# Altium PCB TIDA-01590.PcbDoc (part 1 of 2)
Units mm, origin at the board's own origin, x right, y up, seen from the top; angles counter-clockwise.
Board outline 129.16 x 83.44 mm, 2 copper layers (Top Layer, Bottom Layer), stack 1.646 mm thick; 71 components, 28 nets, 172 pads, 183 vias.
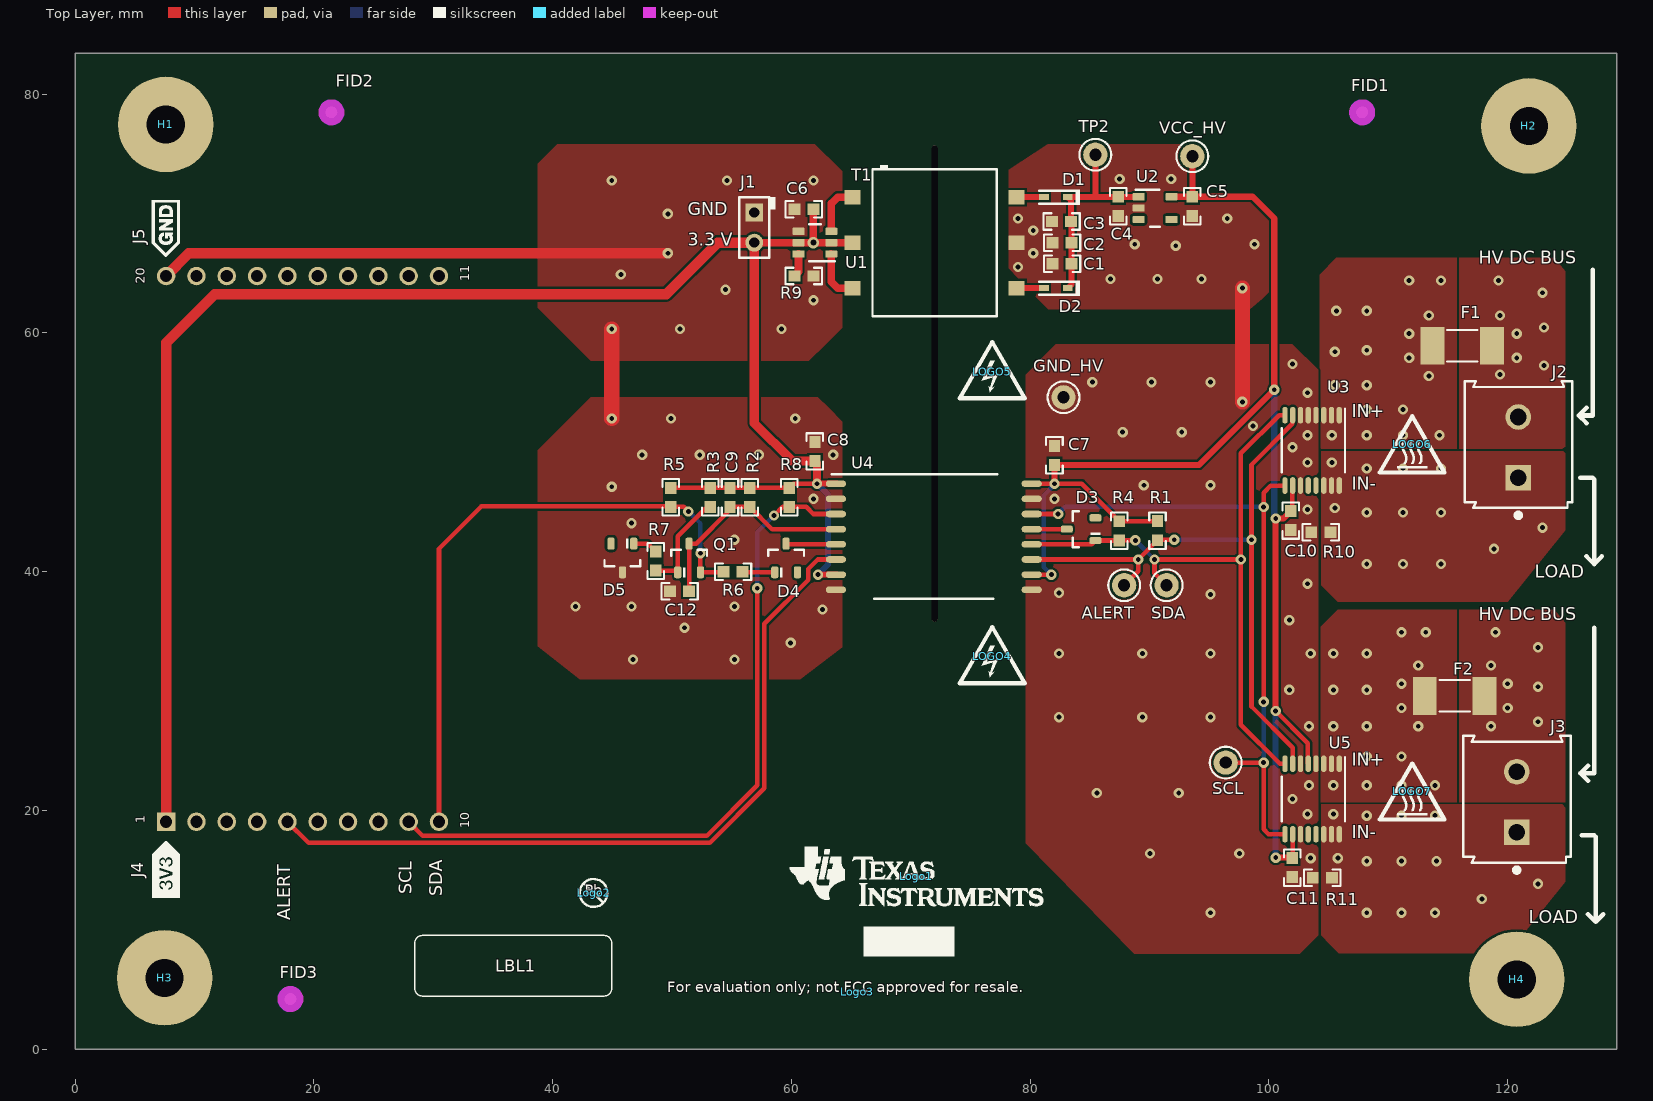
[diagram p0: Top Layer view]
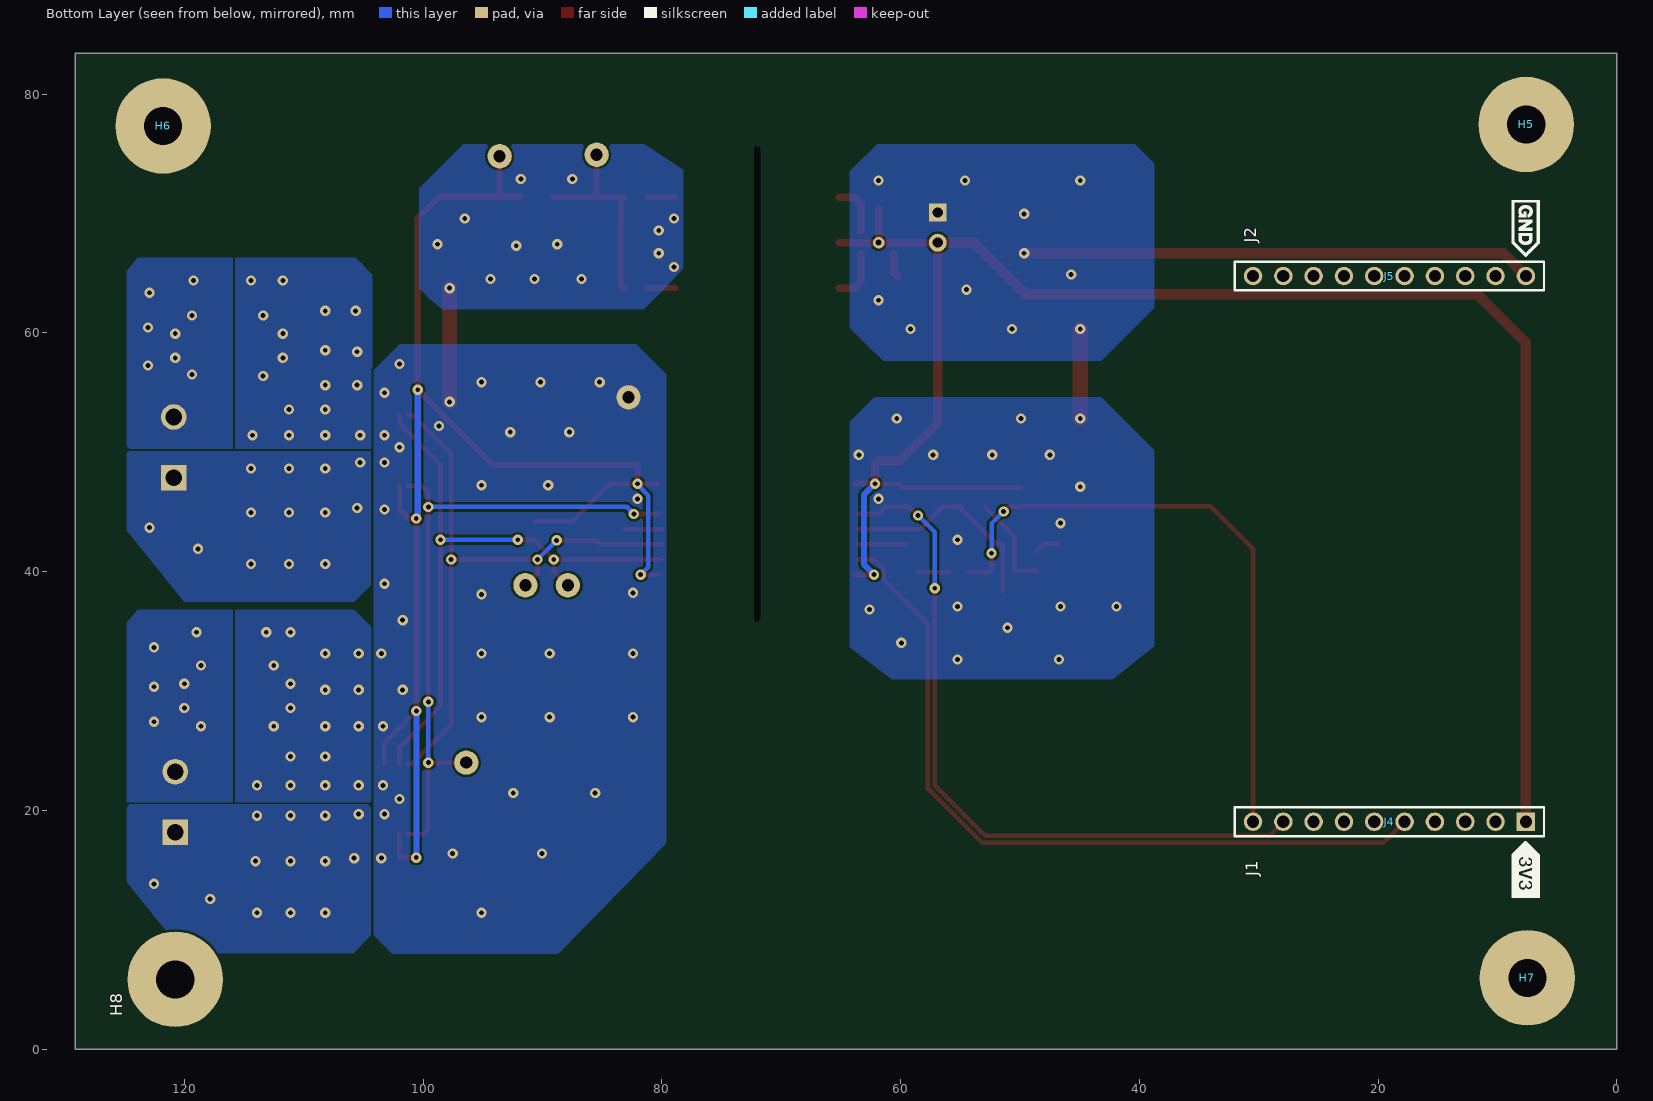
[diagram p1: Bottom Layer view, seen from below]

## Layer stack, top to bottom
Top Solder: solder mask 0.0102, Solder Resist, Dk 3.5
Top Layer: signal copper 0.0711
Dielectric1: core 1.5037, FR-4, Dk 4.8
Bottom Layer: signal copper 0.0711
Bottom Solder: solder mask 0.0102, Solder Resist, Dk 3.5

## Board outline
0,0 129.159,0 129.159,83.439 0,83.439

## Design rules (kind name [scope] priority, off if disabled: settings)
AcuteAngle [All] p1: minimum=4.50000000000000E+0001 checktracksonly=FALSE
AssemblyTestPointUsage [All] p1: valid=2
BoardOutlineClearance BoardOutlineClearance_MountingHoles [OnCopper and InComponentClass('Mounting Holes')] p1: gap=1.016
BoardOutlineClearance BoardOutlineClearance_Poly [OnCopper and IsPoly] p2: gap=0.635
BoardOutlineClearance [OnCopper and Not InComponentClass('Logo') and not InComponentClass('FiducialMark') and not InRegion(1000,500,4000,800) and not InPoly] p3: gap=1.905
Clearance Clearance_Keepouts [((IsTrack Or IsArc) And Not InPoly) And IsFree and IsKeepOut vs ((IsTrack Or IsArc) And Not InPoly) And IsFree and IsKeepOut] p1: gap=0
Clearance Clearance_Poly [InPolygon] p2: gap=0.203
Clearance [All] p3: gap=0.203 except(0.178: Track-THPad SMDPad-SMDPad)
ComponentClearance ComponentClearance_MountingHoles_FiducialMarks [InComponentClass('Mounting Holes') vs InComponentClass('FiducialMark')] p1: gap=1.27 collisioncheckmode=3 verticalgap=0.254 showdistances=FALSE
ComponentClearance ComponentClearance_Shunt [InComponentClass('Header') vs InComponentClass('Shunt')] p2: gap=0 collisioncheckmode=3 verticalgap=0 showdistances=FALSE
ComponentClearance ComponentClearance_Logo [InComponentClass('Logo')] p3: gap=1.27 collisioncheckmode=3 verticalgap=0.254 showdistances=FALSE
ComponentClearance ComponentClearance_ScrewToNut [(HasFootprint('NY PMS 440 0025 PH')) vs (HasFootprint('Keystone_1902C'))] p4: gap=0.127 collisioncheckmode=3 verticalgap=0.254 showdistances=FALSE
ComponentClearance ComponentClearance_MountingHoles [InComponentClass('Mounting Holes')] p5: gap=6.35 collisioncheckmode=3 verticalgap=2540 showdistances=FALSE
ComponentClearance ComponentClearance_SmallPassives [HasFootprint('0201*') or HasFootprint('0402*') or HasFootprint('0508') or HasFootprint('0603*') or HasFootprint('0612') or HasFootprint('0805*') or HasFootprint('0815*') or HasFootprint('0830*') or HasFootprint('1206*') or HasFootprint('1210*') or HasFootprint('1808*') or HasFootprint('1812*') or HasFootprint('1825*') or HasFootprint('2010*') or HasFootprint('2220*') or HasFootprint('2225*') or HasFootprint('2512*') or HasFootprint('2728*') or HasFootprint('3518*') vs HasFootprint('0201*') or HasFootprint('0402*') or HasFootprint('0508') or HasFootprint('0603*') or HasFootprint('0612') or HasFootprint('0805*') or HasFootprint('0815*') or HasFootprint('0830*') or HasFootprint('1206*') or HasFootprint('1210*') or HasFootprint('1808*') or HasFootprint('1812*') or HasFootprint('1825*') or HasFootprint('2010*') or HasFootprint('2220*') or HasFootprint('2225*') or HasFootprint('2512*') or HasFootprint('2728*') or HasFootprint('3518*')] p6: gap=0.38 collisioncheckmode=3 verticalgap=0.254 showdistances=FALSE
ComponentClearance ComponentClearance_THtoSMT [IsThruComponent vs IsSMTComponent] p7: gap=1.016 collisioncheckmode=3 verticalgap=0.762 showdistances=FALSE
ComponentClearance ComponentClearance_THtoTH [IsThruComponent vs IsThruComponent] p8: gap=0.762 collisioncheckmode=3 verticalgap=0.762 showdistances=FALSE
ComponentClearance [All] p9: gap=0.762 collisioncheckmode=3 verticalgap=0.254 showdistances=FALSE
DiffPairsRouting [All] p1: maxlimit=2.54 minlimit=0.254 mostfreqgap=0.254 toplayer_minwidth=0.381 toplayer_maxwidth=0.381 toplayer_prefwidth=0.381 bottomlayer_minwidth=0.381 bottomlayer_maxwidth=0.381 bottomlayer_prefwidth=0.381 maxuncoupledlength=25.4
FabricationTestPointUsage TestPointUsage [All] p1: valid=2 allowmultiple=FALSE
FabricationTestpoint Testpoint [All] p1: side=3 testpointundercomponent=TRUE minsize=1.016 maxsize=2.54 preferedsize=1.524 minholesize=0 maxholesize=1.016 preferedholesize=0.813 testpointgrid=0.025 allowsidetop=TRUE allowsidebottom=TRUE usegrid=TRUE gridtolerance=0
FanoutControl Fanout_LCC [IsLCC] p1: bgadir=Out bgaviamode=Centered fanoutstyle=Auto fanoutdirection=Alternating viagrid=0.025 // Fanout_LCC (Default Rule)
FanoutControl Fanout_BGA [IsBGA] p2: bgadir=Out bgaviamode=Centered fanoutstyle=Auto fanoutdirection=Alternating viagrid=0.025 // Fanout_BGA (Default Rule)
FanoutControl Fanout_Default [All] p4: bgadir=Out bgaviamode=Centered fanoutstyle=Auto fanoutdirection=Alternating viagrid=0.025 // Fanout_Default (Default Rule)
FanoutControl Fanout_Small [(CompPinCount < 5)] p5: bgadir=Out bgaviamode=Centered fanoutstyle=Auto fanoutdirection=OutThenIn viagrid=0.025 // Fanout_Small (Default Rule)
HoleSize [All] p1: absolutevalues=TRUE maxlimit=6.375 minlimit=0.2 maxpercent=80.000 minpercent=20.000
MinimumAnnularRing MinimumAnnularRing_ThermalPadVias [IsVia and InAnyComponent] p1: minimumring=0.15
MinimumAnnularRing [All] p2: minimumring=0.203
MinimumSolderMaskSliver MinimumSolderMaskSliver_Logo [InComponentClass('Logo') vs InComponentClass('Logo')] p1: minsoldermaskwidth=0.018
MinimumSolderMaskSliver [All] p2: minsoldermaskwidth=0.1
PlaneConnect [All] p1: planeconnectstyle=Relief reliefexpansion=0.254 reliefentries=4 reliefconductorwidth=0.254 reliefairgap=0.254
PolygonConnect [All] p1: connectstyle=Direct reliefconductorwidth=0.254 reliefentries=4 polygonreliefangle="90 Angle" airgapwidth=0.254
RoutingVias ThermalPadVias [IsVia and InAnyComponent] p1: holewidth=0.2 width=0.5 viastyle="Through Hole" minholewidth=0.2 minwidth=0.5 maxholewidth=0.33 maxwidth=0.6
RoutingVias [All] p2: holewidth=0.406 width=0.864 viastyle="Through Hole" minholewidth=0.2 minwidth=0.66 maxholewidth=1.016 maxwidth=1.651
SilkToBoardRegionClearance [Not ((IsComment or IsDesignator) And (Hide <> 'False')) and not InRegion(1000,500,4000,800)] p1:
SilkToSilkClearance SilkToSilkClearance_Pb-FreeLogo [(HasFootprint('Pb-Free_Overlay_Medium') OR HasFootprint('Pb-Free_Overlay_Small')) vs (HasFootprint('Pb-Free_Overlay_Medium') OR HasFootprint('Pb-Free_Overlay_Small'))] p1: silktosilkclearance=0
SilkToSilkClearance [All] p2: silktosilkclearance=0.102
SilkToSolderMaskClearance SilkToComponentPadClearance [(IsPad or IsFill or IsRegion) and InAnycomponent] p1: minsilkscreentomaskgap=0.127 clearancetoexposedcopper=TRUE
SilkToSolderMaskClearance "Silk to Solder Mask Opening" [All] p2: minsilkscreentomaskgap=0.102 clearancetoexposedcopper=FALSE
SolderMaskExpansion [All] p1: expansion=0.03
Width [All] p1: maxlimit=2.54 minlimit=0.152 preferedwidth=0.254 checkconnectedcopper=TRUE
15 further rules are at their usual default settings.

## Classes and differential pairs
component class Label: LBL1
component class AssemblyNote: ZZ1 ZZ2 ZZ3 ZZ4
component class FiducialMark: FID1 FID2 FID3
component class EVM_Hardware: FID1 FID2 FID3 H1 H2 H3 H4 H5 H6 H7 H8 LBL1 Logo1 Logo2 Logo3 LOGO4 LOGO5 LOGO6 LOGO7 ZZ1 ZZ2 ZZ3 ZZ4
component class Logo: Logo1
component class "Mounting Holes": H1 H2 H3 H4
component class Current_Sense: ALERT C1 C2 C3 C4 C5 C6 C7 C8 C9 C10 C11 C12 D1 D2 D3 D4 D5 F1 F2 GND_HV J1 J2 J3 J4 J5 J6 Q1 R1 R2 R3 R4 R5 R6 R7 R8 R9 R10 R11 SCL SDA T1 TP2 U1 U2 U3 U4 U5 VCC_HV
component class Header: J1

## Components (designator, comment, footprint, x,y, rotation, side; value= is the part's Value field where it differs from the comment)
ALERT "5000" Keystone5000 87.884,38.862 r90 top (schematic designator TP4)
C1 "GRM188R61C106MAALD" 0603 82.677,65.786 r180 top
C2 "C0603C105K8PACTU" 0603 82.677,67.564 r0 top
C3 "GRM188R71C104KA01D" 0603 82.639,69.342 r180 top
C4 "C1608X7R1E105K080AB" 0603 87.376,70.612 r270 top
C5 "C1608X7R1A225K080AC" 0603 93.599,70.612 r270 top
C6 "GRM188R61C106MAALD" 0603 61.049,70.358 r180 top
C7 "GRM188R71C104KA01D" 0603 82.042,49.746 r270 top
C8 "GRM188R71C104KA01D" 0603 61.976,50.076 r90 top
C9 "0603ZC102KAT2A" 0603 54.864,46.228 r270 top
C10 "GRM188R71C104KA01D" 0603 101.854,44.285 r270 top
C11 "GRM188R71C104KA01D" 0603 101.981,15.202 r270 top
C12 "0603ZC100KAT2A" 0603 50.635,38.354 r180 top
D1 "RB751S40" Fairchild_SOD-523F 82.169,71.374 r180 top
D2 "RB751S40" Fairchild_SOD-523F 82.169,63.754 r180 top
D3 "BAS40-7-F" SOT-23 84.277,43.561 r180 top
D4 "BAS40-7-F" SOT-23 59.563,41.148 r90 top
D5 "BAS40-7-F" SOT-23 45.847,41.148 r270 top
F1 "SSQ 15" Fuse_SSQ 116.205,58.928 r180 top
F2 "SSQ 15" Fuse_SSQ 115.57,29.591 r180 top
FID1 "Fiducial" Fiducial10-20 107.823,78.486 r0 top
FID2 "Fiducial" Fiducial10-20 21.463,78.486 r0 top
FID3 "Fiducial" Fiducial10-20 18.034,4.191 r0 top
GND_HV "5001" Keystone5001 82.804,54.61 r90 top (schematic designator TP3)
H1 "NY PMS 440 0025 PH" "NY PMS 440 0025 PH" 7.593,77.47 r0 top locked
H2 "NY PMS 440 0025 PH" "NY PMS 440 0025 PH" 121.793,77.343 r0 top locked
H3 "NY PMS 440 0025 PH" "NY PMS 440 0025 PH" 7.493,5.969 r0 top locked
H4 "NY PMS 440 0025 PH" "NY PMS 440 0025 PH" 120.777,5.842 r180 top
H5 "1902C" Keystone_1902C#1 7.593,77.47 r180 bottom locked
H6 "1902C" Keystone_1902C#1 121.793,77.343 r180 bottom locked
H7 "1902C" Keystone_1902C#1 7.493,5.969 r180 bottom locked
H8 "1902C" Keystone_1902C#2 120.777,5.842 r0 bottom
J1 "800-10-002-10-001000" Mill-Max_800-10-002-10-001000 56.896,68.834 r270 top
J2 "282841-2" TEC_282841-2 120.904,50.419 r90 top
J3 "282841-2" TEC_282841-2 120.777,20.701 r90 top
J4 "SSQ-110-03-F-S" BoosterPack_20pin_J1 19.05,19.05 r270 bottom
J5 "SSQ-110-03-F-S" BoosterPack_20pin_J2 19.05,64.77 r270 bottom
LBL1 "Size: 0.65\" x 0.20 \"" Label_650x200 36.703,6.985 r0 top
Logo1 "Texas Instruments" TI_Stacked_Overlay_Small 70.485,14.478 r0 top
Logo2 "Pb-Free Symbol" Pb-Free_Overlay_Small 43.434,13.081 r0 top
Logo3 "FCC disclaimer" FCC_disclaimer 65.532,4.826 r0 top
LOGO4 "DANGER HIGH VOLTAGE" IEC_HighVoltage_Small 76.835,32.893 r0 top
LOGO5 "DANGER HIGH VOLTAGE" IEC_HighVoltage_Small 76.835,56.769 r0 top
LOGO6 "CAUTION HOT SURFACE" IEC_HotSurface_Small 112.014,50.673 r0 top
LOGO7 "CAUTION HOT SURFACE" IEC_HotSurface_Small 112.014,21.59 r0 top
Q1 "MMBT3904" SOT-23 51.435,41.148 r90 top
R1 "RC0603FR-077K5L" 0603 90.678,43.434 r90 top
R2 "RT0603BRD073K12L" 0603 56.515,46.228 r270 top
R3 "RT0603BRD072K49L" 0603 53.213,46.228 r90 top
R4 "RT0603BRD071K1L" 0603 87.46,43.423 r90 top
R5 "RT0603BRD071K45L" 0603 49.911,46.228 r90 top
R6 "RT0603BRD0784R5L" 0603 55.118,40.005 r180 top
R7 "RT0603BRD07612RL" 0603 48.641,40.894 r270 top
R8 "RT0603BRD072KL" 0603 59.817,46.228 r90 top
R9 "CRCW06030000Z0EA" 0603 61.049,64.77 r0 top
R10 "CRCW06030000Z0EA" 0603 104.356,43.307 r180 top
R11 "CRCW06030000Z0EA" 0603 104.483,14.351 r180 top
SCL "5000" Keystone5000 96.393,24.003 r90 top (schematic designator TP6)
SDA "5000" Keystone5000 91.44,38.862 r90 top (schematic designator TP5)
T1 "750315240" Wurth_750315240 72.009,67.564 r0 top
TP2 "5000" Keystone5000 85.471,74.93 r90 top
U1 "SN6505ADBVR" DBV0006A_N 61.976,67.564 r180 top
U2 "TPS70933DBVR" DBV0005A_N 90.478,70.459 r0 top
U3 "INA260AIPWR" PW0016A_N 103.632,50.165 r270 top
U4 "ISO7842DWW" DWW0016A_L 71.937,42.926 r0 top
U5 "INA260AIPWR" PW0016A_N 103.632,20.955 r270 top
VCC_HV "5000" Keystone5000 93.599,74.803 r270 top (schematic designator TP1)
ZZ1 "This Assembly Note is for PCB labels only" AssemblyNoteLabel 4.699,97.485 r0 top
ZZ2 "These assemblies are ESD sensitive, ESD precautions shall be observed." AssemblyNote 4.699,94.719 r0 top
ZZ3 "These assemblies must be clean and free from flux and all contaminants. Use of no clean flux is not acceptable." AssemblyNote 4.699,92.47 r0 top
ZZ4 "These assemblies must comply with workmanship standards IPC-A-610 Class 2, unless otherwise specified." AssemblyNote 4.699,90.221 r0 top

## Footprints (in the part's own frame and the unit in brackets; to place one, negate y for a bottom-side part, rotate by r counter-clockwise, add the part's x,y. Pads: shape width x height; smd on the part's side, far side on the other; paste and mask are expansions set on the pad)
0603 [mm] "0603 from SM-752 data"
  rect 1x0.95 smd: 1(-0.8,0) 2(0.8,0)
  silkscreen extent -1.52,-0.69 1.52,0.69, body extent -0.87,-0.47 0.87,0.47, height 1
AssemblyNote [mm] "Assembly Note"
AssemblyNoteLabel [mm] "Assembly Note for PCB Labels"
BoosterPack_20pin_J1 [mm] "Receptacle, 2.54mm, 10x1, TH"
  rrect6% 1.55x1.55 hole 1.02: 1(0,11.43)
  round 1.55 hole 1.02: 2(0,8.89) 3(0,6.35) 4(0,3.81) 5(0,1.27) 6(0,-1.27) 7(0,-3.81) 8(0,-6.35) 9(0,-8.89) 10(0,-11.43)
  silkscreen extent -1.21,-12.95 6.35,12.95, body extent -1.21,-12.95 1.21,12.95, height 8.51
BoosterPack_20pin_J2 [mm] "Receptacle, 2.54mm, 10x1, TH"
  round 1.55 hole 1.02: 11(0,-11.43) 12(0,-8.89) 13(0,-6.35) 14(0,-3.81) 15(0,-1.27) 16(0,1.27) 17(0,3.81) 18(0,6.35) 19(0,8.89) 20(0,11.43)
  silkscreen extent -6.35,-12.95 1.21,12.95, body extent -1.21,-12.95 1.21,12.95, height 8.51
DBV0005A_N [mm] "SOT23, 5-Leads, Body 2.9x1.6mm, Pitch 0.95mm, Lead Span 2.8mm, IPC Medium Density"
  rrect17% 1x0.6 smd: 1(-1.375,0.95) 2(-1.375,0) 3(-1.375,-0.95) 4(1.375,-0.95) 5(1.375,0.95)
  silkscreen extent -1.62,-1.55 0.38,1.55, body extent -1.42,-1.46 1.42,1.46, height 1.09
DBV0006A_N [mm] "SOT23, 6-Leads, Body 2.9x1.6mm, Pitch 0.95mm, Lead Span 2.8mm, IPC Medium Density"
  rrect17% 1x0.6 smd: 1(-1.375,0.95) 2(-1.375,0) 3(-1.375,-0.95) 4(1.375,-0.95) 5(1.375,0) 6(1.375,0.95)
  silkscreen extent -1.67,-1.55 0.5,1.55, body extent -1.42,-1.46 1.42,1.46, height 1.12
DWW0016A_L [mm] "SOP, 16-Leads, Body 10.30x14.00mm, Pitch 1.27mm, IPC High Density"
  oval 1.7x0.55 smd: 1(-8.2,4.445) 2(-8.2,3.175) 3(-8.2,1.905) 4(-8.2,0.635) 5(-8.2,-0.635) 6(-8.2,-1.905) 7(-8.2,-3.175) 8(-8.2,-4.445) 9(8.2,-4.445) 10(8.2,-3.175) 11(8.2,-1.905) 12(8.2,-0.635) 13(8.2,0.635) 14(8.2,1.905) 15(8.2,3.175) 16(8.2,4.445)
  silkscreen extent -8.57,-5.2 5.33,5.22, body extent -8.61,-5.15 8.66,5.15, height 2.47
Fairchild_SOD-523F [mm] "SMD, 2-Leads, Body 1.2x0.8mm"
  rect 0.8x0.5 smd: 1(-1,0) 2(1,0)
  silkscreen extent -2.03,-0.65 1.4,0.65, body extent -0.65,-0.45 0.65,0.45, height 0.7
FCC_disclaimer [mm]
Fiducial10-20 [mm]
  round 1 smd mask+0.5: 1(0,0)
  Top Layer keep-out circle w1.178: c0,0 r0.5
Fuse_SSQ [mm] "Bel Fuse"
  rect 2x3.18 smd: 1(-2.5,0) 2(2.5,0)
  silkscreen extent -1.27,-1.32 1.27,1.32, body extent -3.17,-1.32 3.17,1.32, height 2.64
IEC_HighVoltage_Small [mm]
  silkscreen extent -2.72,-2.24 2.72,2.47
IEC_HotSurface_Small [mm]
  silkscreen extent -2.72,-2.36 2.72,2.35
Keystone5000 [mil] "For Keystone 500x miniature loop terminals"
  round 80 hole 40: 1(0,0)
  silkscreen extent -52,-52 52,52, body extent -49,-49 49,49, height 182
Keystone5001 [mil] "For Keystone 500x miniature loop terminals"
  round 80 hole 40: 1(0,0)
  silkscreen extent -52,-52 52,52, body extent -49,-49 49,49, height 182
Keystone_1902C#1 [mm] "Hex Standoff, 4-40 threaded, nylon"
  body extent -3.68,-3.2 3.71,3.2, height 12.73
Keystone_1902C#2 [mm] "Hex Standoff, 4-40 threaded, nylon"
  round 0.025 on Mech4: 0(0,0)
  body extent -3.68,-3.2 3.71,3.2, height 12.73
Label_650x200 [mm] "Thermal Transfer Label"
  silkscreen extent -8.25,-2.54 8.25,2.54, body extent -8.26,-2.54 8.26,2.54, height 0.03
Mill-Max_800-10-002-10-001000 [mm] "Mill-Max"
  rect 1.5x1.5 hole 0.85: 1(-1.27,0)
  round 1.5 hole 0.85: 2(1.27,0)
  silkscreen extent -2.54,-1.27 2.54,1.78, body extent -2.54,-1.27 2.54,1.27, height 8.13
"NY PMS 440 0025 PH" [mm] "4-40 nylon screw and mounting hole"
  round 8 hole 3.2: 1(0,0)
  body extent -3.3,-3.3 3.3,3.3, height 2.69
Pb-Free_Overlay_Small [mm]
  silkscreen extent -1.16,-1.17 1.17,1.17
PW0016A_N [mm] "TSOP, 16-Leads, Body 5x4.4mm, Pitch 0.65mm, IPC Medium Density"
  oval 1.4x0.45 smd: 1(-2.95,2.275) 2(-2.95,1.625) 3(-2.95,0.975) 4(-2.95,0.325) 5(-2.95,-0.325) 6(-2.95,-0.975) 7(-2.95,-1.625) 8(-2.95,-2.275) 9(2.95,-2.275) 10(2.95,-1.625) 11(2.95,-0.975) 12(2.95,-0.325) 13(2.95,0.325) 14(2.95,0.975) 15(2.95,1.625) 16(2.95,2.275)
  silkscreen extent -3.5,-2.55 1.85,2.75, body extent -3.21,-2.5 3.21,2.5, height 1
SOT-23 [mm] "SOT23, 3-Leads, Body 2.9x1.3mm, Pitch 0.95mm, Lead Span 2.5mm, IPC Medium Density"
  rrect50% 1x0.6 smd: 1(-1.2,0.95) 2(-1.2,-0.95) 3(1.2,0)
  silkscreen extent -1.62,-1.5 0.7,1.5, body extent -1.16,-1.45 1.21,1.45, height 1
TEC_282841-2 [mm] "TE Connectivity"
  rect 2.15x2.15 hole 1.4: 1(-2.54,0)
  round 2.15 hole 1.4: 2(2.54,0)
  silkscreen extent -5.9,-4.52 5.55,4.48, body extent -5.08,-4.53 5.58,4.47, height 15.2
TI_Stacked_Overlay_Small [mm]
  silkscreen extent -10.63,-2.49 10.63,2.49
Wurth_750315240 [mm] "SMD, 6-Leads, Body 10.41x12.32mm"
  rect 1.335x1.215 smd: 1(-6.87,3.81) 2(-6.87,0) 3(-6.87,-3.81) 4(6.87,-3.81) 5(6.87,0) 6(6.87,3.81)
  silkscreen extent -5.21,-6.16 5.21,6.5, body extent -7.43,-6.16 7.43,6.16, height 11.06

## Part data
ALERT SCL SDA TP2 VCC_HV: "Test Point, Miniature, Red, TH"
C1 C6: "CAP, CERM, 10 µF, 16 V, +/- 20%, X5R, 0603"
C2: "CAP, CERM, 1 µF, 10 V, +/- 10%, X5R, 0603"
C3 C7 C8 C10 C11: "CAP, CERM, 0.1 µF, 16 V, +/- 10%, X7R, 0603"
C4: "CAP, CERM, 1 µF, 25 V, +/- 10%, X7R, 0603"
C5: "CAP, CERM, 2.2 µF, 10 V, +/- 10%, X7R, 0603"
C9: "CAP, CERM, 1000 pF, 10 V, +/- 10%, X7R, 0603"
C12: "CAP, CERM, 10 pF, 10 V, +/- 10%, X7R, 0603"
D1 D2: "Diode, Schottky, 40 V, 0.03 A, SOD-523F"
D3 D4 D5: "Diode, Schottky, 40 V, 0.2 A, SOT-23"
F1 F2: "Fuse, 15 A, SMD"
FID1 FID2 FID3: "Fiducial mark.  There is nothing to buy or mount."
GND_HV: "Test Point, Miniature, Black, TH"
H1 H2 H3 H4: "Machine Screw, Round, #4-40 x 1/4, Nylon, Philips panhead"
H5 H6 H7 H8: "Standoff, Hex, 0.5\"L #4-40 Nylon"
J1: "Header, 100mil, 2x1, TH"
J2 J3: "Terminal Block, 2x1, 5.08mm, TH"
J4: library part BoosterPack_20pin_J1, "Receptacle, 2.54mm, 10x1, Gold, TH"
J5: library part BoosterPack_20pin_J2, "Receptacle, 2.54mm, 10x1, Gold, TH"
LBL1: library part THT-14-423-10, "Thermal Transfer Printable Labels, 0.650\" W x 0.200\" H - 10,000 per roll"
Logo1: library part TI_Logo, "Texas Instrument Corporate Signature"
Logo2: library part Pb-Free
Logo3: library part FCC_disclaimer, "FCC_disclaimer"
LOGO4 LOGO5: library part IEC_HighVoltage, "IEC 61010-1 High Voltage Warning"
LOGO6 LOGO7: library part IEC_HotSurface, "IEC 61010-1 Hot Surface Warning"
Q1: library part "MMBT3904, Fairchild Semiconductor", "Transistor, NPN, 40 V, 0.2 A, SOT-23"
R1: "RES, 7.50 k, 1%, 0.1 W, 0603"
R2: "RES, 3.12 k, 0.1%, 0.1 W, 0603"
R3: "RES, 2.49 k, 0.1%, 0.1 W, 0603"
R4: "RES, 1.10 k, 0.1%, 0.1 W, 0603"
R5: "RES, 1.45 k, 0.1%, 0.1 W, 0603"
R6: "RES, 84.5, 0.1%, 0.1 W, 0603"
R7: "RES, 612, 0.1%, 0.1 W, 0603"
R8: "RES, 2.00 k, 0.1%, 0.1 W, 0603"
R9 R10 R11: "RES, 0, 5%, 0.1 W, 0603"
T1: "Transformer, 110 uH, SMT"
U1: "Low-Noise 1-A Transformer Driver for Isolated Power Supplies, Internal Clock-160kHz, DBV0006A (SOT-23-6)"
U2: "150-mA, 30-V, Ultra-Low IQ, Wide Input Low-Dropout Regulator with Reverse Current Protection, DBV0005A (SOT-23-5)"
U3 U5: "Integrated Shunt High-Side or Low-Side Measurement, Bi-Directional Current and Power Monitor with I2C Compatible Interface, PW0016A (TSSOP-16)"
U4: "5.7 kVrms, 100 Mbps, Reinforced 4-Channel 2/2 Digital Isolator, DWW0016A (SOIC-16)"
ZZ1: library part AssemblyNoteLabel
ZZ2 ZZ3 ZZ4: library part AssemblyNote

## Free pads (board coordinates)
  oval 0.483x39.878 hole 0.508 slot 39.878 at 90 deg unplated mask+0.254: 0(72.009,55.753)

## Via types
v1: diameter 0.864, hole 0.406, Top Layer to Bottom Layer, tented both sides, 182 vias
v2: diameter 0.965, hole 0.508, Top Layer to Bottom Layer, tented both sides, 1 vias

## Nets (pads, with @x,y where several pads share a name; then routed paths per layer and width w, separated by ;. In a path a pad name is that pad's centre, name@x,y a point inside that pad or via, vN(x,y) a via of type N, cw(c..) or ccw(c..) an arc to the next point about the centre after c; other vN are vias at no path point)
ALERT: J4.5 U4.6 | length 65
  Top Layer w0.381: J4.5@17.78,19.05 19.558,17.272 53.15,17.272 57.734,21.856 57.734,35.636 61.404,39.306 61.404,40.226 62.2,41.021 U4.6@63.555,41.021
ALERT_HV: ALERT.1 R1.1 U3.7 U4.11 U5.7 | length 54
  Top Layer w0.254: U4.11@79.955,41.021 U4.11@80.209,41.021
  Top Layer w0.381: U4.11@80.209,41.021 v1(89.065,41.021) ; ALERT.1@87.884,38.862 89.065,40.043 v1(89.065,41.021) ; v1(92.075,42.672) 90.716,42.672 R1.1@90.678,42.634 v1(89.065,41.021) ; U5.7@101.976,23.936 U5.7@102.007,23.905 102.007,25.247 98.552,28.702 v1(98.552,42.672) 98.552,48.96 101.976,52.384 101.976,53.084 U3.7@102.007,53.115
  Bottom Layer w0.381: v1(92.075,42.672) v1(98.552,42.672)
GND: C6.2 C8.2 C12.2 D5.3 J1.1 J5.20 R9.2 U1.4 U4.2 U4.8 | length 50.3
  Top Layer w0.889: J5.20@7.62,64.77 9.525,66.675 v1(49.657,66.675)
  Top Layer w1.27: v1(44.958,52.832) v1(44.958,60.325)
  other v1: 46.736,32.639 55.245,32.639 59.944,34.036 51.054,35.306 62.611,36.83 41.91,37.084 46.609,37.084 55.245,37.084 55.245,42.672 46.609,44.069 61.849,46.101 44.958,47.117 47.498,49.784 52.324,49.784 57.277,49.784 63.5,49.784 49.911,52.832 60.325,52.832 50.673,60.325 59.182,60.325 61.849,62.738 54.483,63.627 45.72,64.897 49.657,69.977 44.958,72.771 54.61,72.771 61.849,72.771
GND_HV: C1.2 C2.1 C3.2 C4.2 C5.2 C7.1 C10.2 C11.2 GND_HV.1 R10.2 R11.2 T1.5 U2.2 U3.4 U3.5 U3.6 U3.11 U4.9 U4.15 U5.4 U5.6 U5.11 | length 9.5
  Top Layer w1.27: v1(97.79,54.229) v1(97.79,63.754)
  other v1: 95.123,11.43 103.505,16.002 90.043,16.383 97.536,16.383 103.251,19.685 101.981,20.955 85.598,21.463 92.456,21.463 103.378,22.098 103.378,27.051 82.423,27.813 89.408,27.813 95.123,27.813 101.727,30.099 82.423,33.147 89.408,33.147 95.123,33.147 103.505,33.147 101.727,35.941 95.123,38.1 82.423,38.227 103.251,38.989 103.251,45.212 82.042,46.101 89.535,47.244 95.123,47.244 103.251,49.149 101.981,50.419 103.251,51.435 87.757,51.689 92.71,51.689 98.679,52.197 103.251,54.991 85.217,55.88 90.17,55.88 95.123,55.88 101.981,57.404 86.741,64.516 90.678,64.516 94.361,64.516 78.994,65.532 80.264,66.675 92.202,67.31 88.773,67.437 98.806,67.437 80.264,68.58 78.994,69.596 96.52,69.596 87.503,72.898 91.821,72.898
NetC1_1: C1.1 C2.2 C3.1 C4.1 D1.1 D2.1 TP2.1 U2.1 | length 17.4
  Top Layer w0.508: D2.1@83.169,63.754 83.477,64.062 C1.1@83.477,65.786 C2.2@83.477,67.564 83.477,69.304 C3.1@83.439,69.342 83.439,71.104 D1.1@83.169,71.374 85.471,71.374 ; TP2.1@85.471,74.93 85.471,71.374 ; U2.1@89.103,71.409 89.068,71.374 85.471,71.374
NetD1_2: D1.2 T1.6 | length 2.3
  Top Layer w0.508: T1.6@78.879,71.374 D1.2@81.169,71.374
NetD2_2: D2.2 T1.4 | length 2.3
  Top Layer w0.508: T1.4@78.879,63.754 D2.2@81.169,63.754
NetD4_1: D4.1 R6.1 | length 2.7
  Top Layer w0.254: R6.1@55.918,40.005 R6.1@55.975,39.948
  Top Layer w0.381: R6.1@55.975,39.948 D4.1@58.613,39.948
NetD5_1: D5.1 R7.1 | length 2.1
  Top Layer w0.381: D5.1@46.797,42.348 47.987,42.348 R7.1@48.641,41.694
NetF1_1: F1.1 J2.2
  other v1: 119.38,56.515 123.063,57.277 120.777,57.912 120.777,59.944 123.063,60.452 119.38,61.468 122.936,63.373 119.253,64.389
NetF1_2: F1.2 U3.1 U3.2 U3.3
  other v1: 105.283,51.435 108.204,51.435 111.252,51.435 114.3,51.435 108.204,53.594 111.252,53.594 105.537,55.626 108.204,55.626 113.411,56.388 111.76,57.912 105.537,58.42 108.204,58.547 111.76,59.944 113.411,61.468 105.664,61.849 108.204,61.849 111.76,64.389 114.427,64.389
NetF2_1: F2.1 J3.2
  other v1: 118.618,27.051 122.555,27.432 120.015,28.575 122.555,30.353 120.015,30.607 118.618,32.131 122.555,33.655 118.999,34.925
NetF2_2: F2.2 U5.1 U5.2 U5.3
  other v1: 105.41,22.098 108.204,22.098 111.125,22.098 113.919,22.098 108.204,24.511 111.125,24.511 105.41,27.051 108.204,27.051 112.522,27.051 111.125,28.575 105.41,30.099 108.204,30.099 111.125,30.607 112.522,32.131 105.41,33.147 108.204,33.147 111.125,34.925 113.157,34.925
NetJ2_1: J2.1 R10.1 U3.14 U3.15 U3.16
  other v1: 108.204,40.64 111.252,40.64 114.427,40.64 118.872,41.91 122.936,43.688 108.204,44.958 111.252,44.958 114.427,44.958 105.537,45.339 108.204,48.641 111.252,48.641 114.427,48.641 105.283,49.149
NetJ3_1: J3.1 R11.1 U5.14 U5.15 U5.16
  other v1: 108.204,11.43 111.125,11.43 113.919,11.43 117.856,12.573 122.555,13.843 108.204,15.748 111.125,15.748 114.046,15.748 105.791,16.002 108.204,19.558 111.125,19.558 113.919,19.558 105.41,19.685
NetQ1_1: Q1.1 R3.1 R7.2 | length 8.4
  Top Layer w0.254: Q1.1@50.339,40.094 Q1.1@50.485,39.948
  Top Layer w0.381: R7.2@48.641,40.094 Q1.1@50.339,40.094 ; Q1.1@50.485,39.948 50.485,42.954 R3.1@52.959,45.428
NetR9_1: R9.1 U1.6 | length 2
  Top Layer w0.635: R9.1@60.249,64.77 60.601,65.122 U1.6@60.601,66.614
NetT1_1: T1.1 U1.3 | length 4.3
  Top Layer w0.635: U1.3@63.351,68.514 63.351,70.844 63.881,71.374 T1.1@65.139,71.374
NetT1_3: T1.3 U1.1 | length 4.3
  Top Layer w0.635: U1.1@63.351,66.614 63.351,64.284 63.881,63.754 T1.3@65.139,63.754
SCL: J4.9 R8.1 U4.3 | length 60.2
  Top Layer w0.381: J4.9@27.94,19.05 29.134,17.856 52.908,17.856 57.15,22.098 v1(57.15,38.608) ; v1(58.547,44.704) 59.271,45.428 R8.1@59.817,45.428 61.245,45.428 61.842,44.831 U4.3@63.555,44.831
  Bottom Layer w0.254: v1@58.531,44.704 v1(58.547,44.704)
  Bottom Layer w0.381: v1(57.15,38.608) 57.15,43.273 57.125,43.298 v1@58.531,44.704
SCL_HV: SCL.1 U3.9 U4.14 U5.9 | length 55
  Top Layer w0.381: U4.14@80.209,44.831 v1(82.352,44.831) ; SCL.1@96.393,24.003 v1(99.568,24.003) 99.568,18.415 99.978,18.005 U5.9@101.357,18.005 ; v1(99.568,29.095) v1(99.568,45.426) 99.568,46.609 100.174,47.215 U3.9@101.357,47.215
  Bottom Layer w0.381: v1(82.352,44.831) 82.947,45.426 v1(99.568,45.426) ; v1(99.568,24.003) v1(99.568,29.095)
SDA: J4.10 Q1.2 R5.1 R6.2 | length 52.9
  Top Layer w0.254: R6.2@54.261,39.948 R6.2@54.318,40.005
  Top Layer w0.381: J4.10@30.48,19.05 30.48,41.91 34.036,45.466 R5.1@49.911,45.466 ; R5.1@49.911,45.428 50.995,45.428 v1(51.375,45.048) ; v1(52.385,41.538) Q1.2@52.385,39.948 R6.2@54.261,39.948
  Bottom Layer w0.381: v1(51.375,45.048) 52.385,44.038 v1(52.385,41.538)
SDA_HV: D3.1 R4.1 SDA.1 U3.8 U4.12 U5.8 | length 53.9
  Top Layer w0.254: R4.1@87.448,42.611 R4.1@87.46,42.623
  Top Layer w0.381: U4.12@79.955,42.291 85.157,42.291 D3.1@85.477,42.611 R4.1@87.448,42.611 ; R4.1@87.46,42.623 v1(88.822,42.623) ; SDA.1@91.44,38.862 90.424,39.878 v1(90.424,41.021) v1(97.663,41.021) ; U5.8@101.357,23.905 100.936,23.905 97.663,27.178 v1(97.663,41.021) ; U3.8@101.357,53.115 100.867,53.115 97.663,49.911 v1(97.663,41.021)
  Bottom Layer w0.381: v1(88.822,42.623) v1(90.424,41.021)
SDA_HVIN: D3.3 U4.13 | length 3.1
  Top Layer w0.381: U4.13@79.955,43.561 D3.3@83.077,43.561
SDA_IN: C9.2 C12.1 Q1.3 R2.2 U4.4 | length 18.3
  Top Layer w0.381: C12.1@51.435,38.354 Q1.3@51.435,42.348 52.028,42.348 54.864,45.184 C9.2@54.864,45.428 R2.2@56.515,45.428 58.382,43.561 U4.4@63.555,43.561
SDA_OUT: D4.3 U4.5 | length 3.9
  Top Layer w0.381: D4.3@59.62,42.291 U4.5@63.555,42.291
VCC: C6.1 C8.1 C9.1 J1.2 J4.1 R2.1 R3.2 R5.2 R8.2 T1.2 U1.2 U1.5 U4.1 U4.7 | length 151.4
  Top Layer w0.381: R5.2@49.911,47.028 R3.2@53.213,47.028 R2.1@56.515,47.028 R8.2@59.817,47.028 60.16,47.371 v1(62.153,47.371)
  Top Layer w0.508: C8.1@61.976,49.276 C8.1@62.153,49.099 ; v1(62.153,47.371) U4.1@63.809,47.371 ; v1(62.23,39.751) U4.7@63.809,39.751
  Top Layer w0.635: J1.2@56.896,67.564 U1.5@60.601,67.564 v2(61.849,67.564) ; C6.1@61.849,70.358 v2(61.849,67.564) ; v1(62.153,47.371) C8.1@62.153,49.099 ; T1.2@65.139,67.564 U1.2@63.351,67.564 v2(61.849,67.564)
  Top Layer w0.762: J1.2@56.896,67.564 56.896,52.451 60.071,49.276 C8.1@61.976,49.276
  Top Layer w0.889: J4.1@7.62,19.05 7.62,59.182 11.684,63.246 49.53,63.246 53.848,67.564 J1.2@56.896,67.564
  Bottom Layer w0.508: v1(62.153,47.371) 63.089,46.435 63.089,40.61 v1(62.23,39.751)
